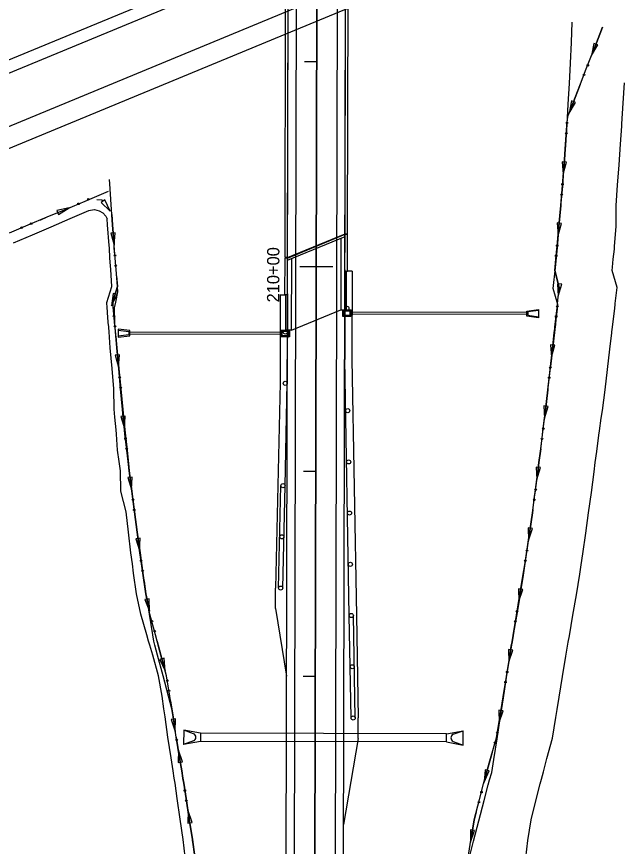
# Model space of a CAD drawing. Extents: x 1611108 to 1749517, y 619561 to 797725.
# Drawn here: x 1717467 to 1717763.5, y 765954.9 to 766360 of the extents above; entities that cross this region are included whole.
import ezdxf

# ---------------------------------------------------------------- set-up
doc = ezdxf.new("R2010")
doc.units = 0
for name, color, linetype in [('Level 8', 7, 'Continuous'), ('R_Bridge', 7, 'Continuous'), ('R_Ditch', 7, 'Continuous'), ('R_Drainage', 7, 'Continuous'), ('R_Guardrail', 7, 'Continuous'), ('R_Horz Alg', 7, 'Continuous'), ('R_Horz Alg Stationing_Side Road', 7, 'Continuous'), ('R_Proposed Const Limits', 7, 'Continuous'), ('R_Proposed Road', 7, 'Continuous'), ('R_Shld_GR', 7, 'Continuous'), ('R_Special Ditch', 7, 'Continuous')]:
    doc.layers.add(name, color=color, linetype=linetype)

msp = doc.modelspace()

# ---------------------------------------------------------------- linework, layer by layer
at = {"layer": 'Level 8'}
msp.add_line((1717616.46, 767638.01), (1717610.87, 765238.01), dxfattribs=at)
at = {"layer": 'R_Bridge'}
for p, q in [((1717627.24, 766253.93), (1717628.19, 766664.7)), ((1717628.49, 766253.93), (1717629.44, 766664.7)), ((1717597.96, 766242.32), (1717598.91, 766653.1)), ((1717599.21, 766242.32), (1717600.16, 766653.09)), ((1717599.21, 766242.32), (1717627.24, 766253.93)), ((1717627.24, 766253.93), (1717628.49, 766253.93)), ((1717599.21, 766242.09), (1717627.23, 766253.7)), ((1717599.21, 766241.01), (1717627.23, 766252.62)), ((1717627.19, 766235.7), (1717627.23, 766253.7)), ((1717627.23, 766253.7), (1717628.48, 766253.7)), ((1717628.44, 766235.7), (1717628.48, 766253.7)), ((1717597.92, 766224.1), (1717597.96, 766242.1)), ((1717599.21, 766242.32), (1717597.96, 766242.32)), ((1717599.21, 766242.09), (1717597.96, 766242.1)), ((1717599.17, 766224.09), (1717599.21, 766242.09)), ((1717627.19, 766235.7), (1717628.44, 766235.7)), ((1717599.17, 766224.09), (1717597.92, 766224.1))]:
    msp.add_line(p, q, dxfattribs=at)
at = {"layer": 'R_Ditch'}
for p, q in [((1717748.63, 766346.88), (1717747.45, 766340.9)), ((1717747.45, 766340.9), (1717750.6, 766346.11)), ((1717750.6, 766346.11), (1717748.63, 766346.88)), ((1717737.76, 766318.87), (1717736.57, 766312.9)), ((1717739.73, 766318.11), (1717737.76, 766318.87)), ((1717736.57, 766312.9), (1717739.73, 766318.11)), ((1717735.2, 766288.97), (1717733.09, 766289.13)), ((1717733.09, 766289.13), (1717733.69, 766283.07)), ((1717733.69, 766283.07), (1717735.2, 766288.97)), ((1717510.07, 766270.49), (1717508.34, 766269.28)), ((1717512.65, 766264.97), (1717510.07, 766270.49)), ((1717492.61, 766266.61), (1717486.67, 766265.27)), ((1717487.49, 766263.31), (1717492.61, 766266.61)), ((1717508.34, 766269.28), (1717512.65, 766264.97)), ((1717486.67, 766265.27), (1717487.49, 766263.31)), ((1717732.75, 766259.01), (1717730.65, 766259.21)), ((1717730.65, 766259.21), (1717731.15, 766253.14)), ((1717731.15, 766253.14), (1717732.75, 766259.01)), ((1717515.16, 766254.39), (1717513.05, 766254.23)), ((1717513.05, 766254.23), (1717514.56, 766248.33)), ((1717514.56, 766248.33), (1717515.16, 766254.39)), ((1717732.97, 766229.35), (1717730.86, 766229.57)), ((1717730.86, 766229.57), (1717731.28, 766223.5)), ((1717731.28, 766223.5), (1717732.97, 766229.35)), ((1717514.09, 766224.84), (1717513.34, 766218.79)), ((1717513.34, 766218.79), (1717516.11, 766224.22)), ((1717516.11, 766224.22), (1717514.09, 766224.84)), ((1717729.63, 766199.49), (1717727.52, 766199.73)), ((1717727.52, 766199.73), (1717727.9, 766193.65)), ((1717727.9, 766193.65), (1717729.63, 766199.49)), ((1717517.27, 766194.88), (1717515.17, 766194.69)), ((1717515.17, 766194.69), (1717516.77, 766188.81)), ((1717516.77, 766188.81), (1717517.27, 766194.88)), ((1717726.27, 766169.64), (1717724.17, 766169.88)), ((1717724.17, 766169.88), (1717724.52, 766163.8)), ((1717724.52, 766163.8), (1717726.27, 766169.64)), ((1717520.05, 766164.98), (1717517.94, 766164.77)), ((1717519.59, 766158.91), (1717520.05, 766164.98)), ((1717517.94, 766164.77), (1717519.59, 766158.91)), ((1717722.62, 766139.81), (1717720.52, 766140.08)), ((1717720.52, 766140.08), (1717720.81, 766133.99)), ((1717720.81, 766133.99), (1717722.62, 766139.81)), ((1717523.4, 766135.16), (1717521.3, 766134.9)), ((1717521.3, 766134.9), (1717523.08, 766129.07)), ((1717523.08, 766129.07), (1717523.4, 766135.16)), ((1717718.63, 766110.02), (1717716.53, 766110.33)), ((1717716.53, 766110.33), (1717716.69, 766104.24)), ((1717716.69, 766104.24), (1717718.63, 766110.02)), ((1717527.25, 766105.38), (1717525.16, 766105.09)), ((1717525.16, 766105.09), (1717527.02, 766099.29)), ((1717527.02, 766099.29), (1717527.25, 766105.38)), ((1717713.99, 766080.32), (1717711.9, 766080.67)), ((1717711.9, 766080.67), (1717711.95, 766074.58)), ((1717711.95, 766074.58), (1717713.99, 766080.32)), ((1717531.68, 766075.73), (1717529.6, 766075.33)), ((1717531.78, 766069.64), (1717531.68, 766075.73)), ((1717529.6, 766075.33), (1717531.78, 766069.64)), ((1717709.1, 766050.69), (1717707.01, 766051.03)), ((1717707.01, 766051.03), (1717707.09, 766044.94)), ((1717707.09, 766044.94), (1717709.1, 766050.69)), ((1717538.95, 766046.68), (1717536.9, 766046.13)), ((1717536.9, 766046.13), (1717539.48, 766040.61)), ((1717539.48, 766040.61), (1717538.95, 766046.68)), ((1717704.32, 766021.04), (1717702.23, 766021.37)), ((1717702.23, 766021.37), (1717702.36, 766015.27)), ((1717702.36, 766015.27), (1717704.32, 766021.04)), ((1717544.59, 766017.09), (1717542.49, 766016.77)), ((1717542.49, 766016.77), (1717544.45, 766011)), ((1717544.45, 766011), (1717544.59, 766017.09)), ((1717695.56, 765992.24), (1717695.05, 765986.17)), ((1717695.05, 765986.17), (1717697.61, 765991.7)), ((1717697.61, 765991.7), (1717695.56, 765992.24)), ((1717690.46, 765962.63), (1717688.37, 765963)), ((1717688.37, 765963), (1717688.38, 765956.9)), ((1717688.38, 765956.9), (1717690.46, 765962.63))]:
    msp.add_line(p, q, dxfattribs=at)
for points in [[(1717687.85, 765948.93), (1717689.95, 765957.36), (1717692.47, 765967.35), (1717695.03, 765977.34), (1717697, 765984.91), (1717697.74, 765987.34), (1717698.83, 765990.91), (1717699.87, 765997.33), (1717701.4, 766007.33), (1717702.91, 766017.33), (1717703.5, 766021.2), (1717704.46, 766027.32), (1717706.06, 766037.32), (1717707.68, 766047.32), (1717708.47, 766052.2), (1717708.81, 766054.21), (1717709.32, 766057.31), (1717710.99, 766067.31), (1717712.42, 766075.87), (1717712.65, 766077.3), (1717714.25, 766087.3), (1717715.78, 766097.3), (1717717.24, 766107.29), (1717718.62, 766117.29), (1717719.73, 766125.86), (1717719.93, 766127.29), (1717721.26, 766137.28), (1717721.51, 766139.18), (1717722.54, 766147.28), (1717723.78, 766157.28), (1717724.96, 766167.28), (1717726.12, 766177.27), (1717727.37, 766187.27), (1717727.61, 766189.17), (1717728.58, 766197.27), (1717729.74, 766207.26), (1717729.78, 766207.55), (1717729.81, 766207.81), (1717729.81, 766207.83), (1717729.84, 766208.12), (1717730.26, 766211.87), (1717730.86, 766217.26), (1717731.04, 766218.99), (1717731.09, 766219.49), (1717728.84, 766227.27), (1717729.85, 766237.26), (1717730.81, 766247.26), (1717731.72, 766257.26), (1717732.58, 766267.26), (1717733.4, 766277.26), (1717734.16, 766287.25), (1717734.87, 766297.25), (1717735.54, 766307.25), (1717736.15, 766317.25), (1717736.71, 766327.25), (1717737.23, 766337.25), (1717737.69, 766347.25), (1717738.11, 766357.25)], [(1717687.33, 765949.41), (1717688.55, 765957.83), (1717690.29, 765967.83), (1717692.86, 765977.82), (1717694.84, 765985.39), (1717695.48, 765987.82), (1717696.43, 765991.39), (1717698.15, 765997.81), (1717701.06, 766007.81), (1717702.75, 766017.8), (1717703.35, 766021.67), (1717704.31, 766027.8), (1717705.92, 766037.79), (1717707.55, 766047.79), (1717708.35, 766052.68), (1717708.68, 766054.68), (1717709.18, 766057.79), (1717710.81, 766067.78), (1717712.49, 766077.78), (1717714.13, 766087.78), (1717714.87, 766092.34), (1717715.71, 766097.77), (1717717.22, 766107.77), (1717718.65, 766117.77), (1717720.01, 766127.76), (1717721.29, 766137.76), (1717721.85, 766142.33), (1717722.54, 766147.76), (1717723.53, 766155.65), (1717723.79, 766157.75), (1717724.53, 766163.96), (1717724.98, 766167.75), (1717726.13, 766177.75), (1717727.22, 766187.75), (1717728.36, 766197.74), (1717729.29, 766205.64), (1717729.54, 766207.74), (1717729.57, 766208.03), (1717729.6, 766208.29), (1717729.6, 766208.3), (1717729.63, 766208.59), (1717730.06, 766212.34), (1717730.66, 766217.74), (1717730.85, 766219.46), (1717730.9, 766219.96), (1717731.73, 766227.73), (1717729.5, 766236.02), (1717729.67, 766237.74), (1717730.05, 766241.56), (1717730.53, 766246.54), (1717730.65, 766247.74), (1717731.57, 766257.74), (1717732.45, 766267.73), (1717733.27, 766277.73), (1717734.05, 766287.73), (1717734.77, 766297.73), (1717735.38, 766306.62), (1717735.45, 766307.73), (1717736.07, 766311.61), (1717742.09, 766327.13), (1717744.94, 766334.41), (1717749.39, 766345.92), (1717752.9, 766354.87)], [(1717752.9, 766354.87), (1717749.39, 766345.92), (1717747.45, 766340.9)], [(1717742, 766326.88), (1717736.57, 766312.9)], [(1717742.01, 766326.92), (1717742, 766326.88)], [(1717734.79, 766298.03), (1717734.77, 766297.73), (1717734.05, 766287.73), (1717733.69, 766283.07)], [(1717734.79, 766298.06), (1717734.79, 766298.03)], [(1717553.97, 765949.72), (1717552.75, 765958.15), (1717551.26, 765968.15), (1717549.73, 765978.16), (1717548.55, 765985.73), (1717548.16, 765988.16), (1717547.59, 765991.74), (1717546.55, 765998.17), (1717544.89, 766008.17), (1717543.35, 766018.17), (1717542.74, 766022.04), (1717541.13, 766028.18), (1717538.46, 766038.18), (1717535.77, 766048.19), (1717534.45, 766053.08), (1717533.91, 766055.09), (1717533.4, 766058.2), (1717531.8, 766068.2), (1717530.5, 766076.77), (1717530.28, 766078.2), (1717528.8, 766088.21), (1717527.38, 766098.21), (1717526, 766108.21), (1717524.67, 766118.22), (1717523.57, 766126.79), (1717523.39, 766128.22), (1717522.16, 766138.22), (1717521.93, 766140.12), (1717521.04, 766148.22), (1717520.02, 766158.23), (1717519.03, 766168.23), (1717518.01, 766178.23), (1717517.06, 766188.23), (1717516.88, 766190.13), (1717516.03, 766198.24), (1717515.02, 766208.24), (1717514.99, 766208.53), (1717514.96, 766208.79), (1717514.83, 766217.84), (1717515.47, 766220.55), (1717516.47, 766225.61), (1717516.23, 766228.24), (1717515.52, 766236.52), (1717515.37, 766238.24), (1717515.06, 766242.06), (1717514.56, 766248.24), (1717513.8, 766258.24), (1717513.09, 766268.24), (1717512.43, 766278.25), (1717512.3, 766280.43)], [(1717463.5, 766254.41), (1717472.72, 766258.27), (1717481.94, 766262.14), (1717491.17, 766266), (1717500.39, 766269.86), (1717509.62, 766273.71), (1717511.92, 766274.67)], [(1717506.23, 766270.75), (1717508.64, 766270.45), (1717509.28, 766269.95)], [(1717478.78, 766260.81), (1717481.94, 766262.14), (1717491.17, 766266), (1717492.61, 766266.61)], [(1717732.48, 766268.08), (1717732.45, 766267.73), (1717731.57, 766257.74), (1717731.15, 766253.14)], [(1717732.48, 766268.12), (1717732.48, 766268.08)], [(1717553.97, 765949.72), (1717552.75, 765958.15), (1717551.26, 765968.15), (1717549.73, 765978.16), (1717548.55, 765985.73), (1717548.16, 765988.16), (1717547.59, 765991.74), (1717546.55, 765998.17), (1717544.89, 766008.17), (1717543.35, 766018.17), (1717542.74, 766022.04), (1717541.77, 766028.18), (1717540.14, 766038.18), (1717537.45, 766048.19), (1717536.13, 766053.08), (1717535.59, 766055.09), (1717534.75, 766058.19), (1717532.06, 766068.2), (1717530.12, 766078.2), (1717528.6, 766088.21), (1717527.94, 766092.78), (1717527.17, 766098.21), (1717525.79, 766108.21), (1717524.46, 766118.22), (1717523.18, 766128.22), (1717521.95, 766138.22), (1717521.41, 766142.79), (1717520.77, 766148.23), (1717519.88, 766156.13), (1717519.66, 766158.23), (1717519.04, 766164.44), (1717518.67, 766168.23), (1717517.76, 766178.23), (1717516.82, 766188.23), (1717515.9, 766198.24), (1717515.23, 766206.14), (1717515.02, 766208.24), (1717514.99, 766208.53), (1717514.97, 766208.79), (1717514.96, 766208.8), (1717514.94, 766209.09), (1717514.57, 766212.85), (1717514.06, 766218.24), (1717513.9, 766219.97), (1717513.85, 766220.47), (1717516.23, 766228.24), (1717515.52, 766236.52), (1717515.37, 766238.24), (1717515.06, 766242.06), (1717514.66, 766247.04), (1717514.56, 766248.24), (1717513.8, 766258.24), (1717513.44, 766263.29)], [(1717513.44, 766263.29), (1717513.8, 766258.24), (1717514.56, 766248.33)], [(1717478.74, 766260.8), (1717478.78, 766260.81)], [(1717729.72, 766238.17), (1717729.67, 766237.74), (1717729.5, 766236.02), (1717731.73, 766227.73), (1717731.28, 766223.5)], [(1717729.72, 766238.2), (1717729.72, 766238.17)], [(1717515.79, 766233.34), (1717516.23, 766228.24), (1717513.85, 766220.47), (1717513.9, 766219.97), (1717514.02, 766218.72)], [(1717515.79, 766233.38), (1717515.79, 766233.34)], [(1717729.63, 766208.55), (1717729.6, 766208.3), (1717729.6, 766208.29), (1717729.57, 766208.03), (1717729.54, 766207.74), (1717729.29, 766205.64), (1717728.36, 766197.74), (1717727.9, 766193.65)], [(1717729.63, 766208.59), (1717729.63, 766208.55)], [(1717515.43, 766203.79), (1717515.43, 766203.75)], [(1717515.43, 766203.75), (1717515.9, 766198.24), (1717516.77, 766188.81)], [(1717726.23, 766178.7), (1717726.13, 766177.75), (1717724.98, 766167.75), (1717724.53, 766163.96), (1717724.52, 766163.8)], [(1717726.24, 766178.74), (1717726.23, 766178.7)], [(1717518.16, 766173.87), (1717518.16, 766173.84)], [(1717518.16, 766173.84), (1717518.67, 766168.23), (1717519.04, 766164.44), (1717519.59, 766158.91)], [(1717722.68, 766148.88), (1717722.54, 766147.76), (1717721.85, 766142.33), (1717721.29, 766137.76), (1717720.81, 766133.99)], [(1717722.69, 766148.91), (1717722.68, 766148.88)], [(1717521.27, 766144), (1717521.27, 766143.96)], [(1717521.27, 766143.96), (1717521.41, 766142.79), (1717521.95, 766138.22), (1717523.08, 766129.07)], [(1717718.83, 766119.09), (1717718.65, 766117.77), (1717717.22, 766107.77), (1717716.69, 766104.24)], [(1717718.84, 766119.12), (1717718.83, 766119.09)], [(1717525, 766114.19), (1717525, 766114.16)], [(1717525, 766114.16), (1717525.79, 766108.21), (1717527.02, 766099.29)], [(1717714.39, 766089.38), (1717714.13, 766087.78), (1717712.49, 766077.78), (1717711.95, 766074.58)], [(1717714.4, 766089.42), (1717714.39, 766089.38)], [(1717529.17, 766084.45), (1717529.18, 766084.41)], [(1717529.18, 766084.41), (1717530.12, 766078.2), (1717531.78, 766069.64)], [(1717709.5, 766059.74), (1717709.18, 766057.79), (1717708.68, 766054.68), (1717708.35, 766052.68), (1717707.55, 766047.79), (1717707.09, 766044.94)], [(1717709.51, 766059.78), (1717709.5, 766059.74)], [(1717535.58, 766055.13), (1717535.59, 766055.1)], [(1717535.59, 766055.1), (1717535.59, 766055.09), (1717536.13, 766053.08), (1717537.45, 766048.19), (1717539.48, 766040.61)], [(1717704.68, 766030.09), (1717704.31, 766027.8), (1717703.35, 766021.67), (1717702.75, 766017.8), (1717702.32, 766015.28)], [(1717704.69, 766030.13), (1717704.68, 766030.09)], [(1717542.14, 766025.86), (1717542.14, 766025.82)], [(1717542.14, 766025.82), (1717542.74, 766022.04), (1717543.35, 766018.17), (1717544.45, 766011)], [(1717553.97, 765949.72), (1717552.75, 765958.15), (1717551.26, 765968.15), (1717549.73, 765978.16), (1717548.55, 765985.73), (1717548.16, 765988.16), (1717547.59, 765991.74), (1717546.55, 765998.17), (1717544.89, 766008.17)], [(1717698.97, 766000.65), (1717698.15, 765997.81), (1717696.43, 765991.39), (1717695.48, 765987.82), (1717695.05, 765986.17)], [(1717698.98, 766000.68), (1717698.97, 766000.65)], [(1717691.26, 765971.62), (1717690.29, 765967.83), (1717688.55, 765957.83), (1717688.41, 765956.9)], [(1717691.27, 765971.65), (1717691.26, 765971.62)]]:
    msp.add_lwpolyline(points, dxfattribs=at)
for centre in [(1717745.68, 766336.22), (1717743.86, 766331.55), (1717735.53, 766308.03), (1717735.17, 766303.03), (1717733.33, 766278.07), (1717501.99, 766270.77), (1717732.92, 766273.08), (1717497.22, 766268.57), (1717474.13, 766258.91), (1717469.51, 766256.97), (1717730.72, 766248.15), (1717514.99, 766243.34), (1717730.24, 766243.16), (1717515.4, 766238.35), (1717730.78, 766218.51), (1717514.52, 766213.74), (1717730.23, 766213.54), (1717515.01, 766208.76), (1717727.36, 766188.67), (1717517.27, 766183.83), (1717726.81, 766183.69), (1717517.74, 766178.84), (1717723.95, 766158.83), (1717520.16, 766153.93), (1717723.34, 766153.86), (1717520.73, 766148.95), (1717720.21, 766129.02), (1717523.75, 766124.11), (1717719.54, 766124.06), (1717524.38, 766119.14), (1717715.98, 766099.29), (1717527.76, 766094.34), (1717715.21, 766094.33), (1717528.47, 766089.38), (1717711.16, 766069.64), (1717533.02, 766064.79), (1717710.35, 766064.69), (1717534.32, 766059.96), (1717706.32, 766039.99), (1717540.57, 766035.73), (1717705.52, 766035.05), (1717541.38, 766030.79), (1717701.52, 766010.34), (1717700.41, 766005.46), (1717693.81, 765981.32), (1717692.55, 765976.47)]:
    msp.add_circle(centre, 0.375, dxfattribs=at)
at = {"layer": 'R_Drainage'}
for p, q in [((1717715.92, 766214.46), (1717629.64, 766214.66)), ((1717715.93, 766215.46), (1717629.65, 766215.66)), ((1717596.62, 766205.74), (1717522.2, 766205.91)), ((1717596.62, 766204.74), (1717522.2, 766204.91)), ((1717548.53, 766011.66), (1717548.51, 766004.66)), ((1717556.7, 766010.14), (1717548.53, 766011.66)), ((1717553.34, 766009.87), (1717548.53, 766011.66)), ((1717676.7, 766009.86), (1717684.87, 766011.34)), ((1717680.06, 766009.57), (1717684.87, 766011.34)), ((1717684.85, 766004.34), (1717684.87, 766011.34)), ((1717556.7, 766010.14), (1717556.69, 766006.14)), ((1717676.7, 766009.86), (1717556.7, 766010.14)), ((1717676.69, 766005.86), (1717676.7, 766009.86)), ((1717553.33, 766006.43), (1717548.51, 766004.66)), ((1717556.69, 766006.14), (1717548.51, 766004.66)), ((1717676.69, 766005.86), (1717556.69, 766006.14)), ((1717676.69, 766005.86), (1717684.85, 766004.34)), ((1717680.05, 766006.13), (1717684.85, 766004.34))]:
    msp.add_line(p, q, dxfattribs=at)
for points in [[(1717630.15, 766216.78), (1717630.14, 766213.55), (1717626.14, 766213.56), (1717626.15, 766216.79)], [(1717629.65, 766216.28), (1717629.64, 766214.05), (1717626.64, 766214.06), (1717626.65, 766216.29)], [(1717715.93, 766216.21), (1717721.6, 766216.95), (1717721.59, 766212.95), (1717715.92, 766213.71)], [(1717522.21, 766206.66), (1717516.54, 766207.42), (1717516.53, 766203.42), (1717522.2, 766204.16)], [(1717600.13, 766206.84), (1717600.12, 766203.61), (1717596.12, 766203.62), (1717596.13, 766206.85)], [(1717599.62, 766206.34), (1717599.62, 766204.11), (1717596.62, 766204.12), (1717596.62, 766206.35)]]:
    msp.add_lwpolyline(points, close=True, dxfattribs=at)
for points in [[(1717721.6, 766216.45), (1717716.43, 766215.77), (1717716.42, 766214.15), (1717721.59, 766213.46)], [(1717516.54, 766206.92), (1717521.7, 766206.22), (1717521.7, 766204.6), (1717516.53, 766203.93)]]:
    msp.add_lwpolyline(points, dxfattribs=at)
for centre, start, end in [((1717552.69, 766008.15), 290.1852, 69.548), ((1717680.69, 766007.85), 110.1852, 249.548)]:
    msp.add_arc(centre, 1.83, start, end, dxfattribs=at)
at = {"layer": 'R_Guardrail'}
for p, q in [((1717627.19, 766236.3), (1717627.09, 766192.55)), ((1717599.17, 766224.69), (1717599.07, 766181.13)), ((1717629.3, 766067.55), (1717627.09, 766192.55)), ((1717597.95, 766130.94), (1717599.07, 766181.13)), ((1717594.83, 766080.99), (1717595.95, 766130.99)), ((1717596.83, 766080.95), (1717597.95, 766130.94)), ((1717632.18, 766017.58), (1717631.3, 766067.58)), ((1717630.19, 766017.54), (1717629.3, 766067.55))]:
    msp.add_line(p, q, dxfattribs=at)
for centre in [(1717628.15, 766217.57), (1717598.12, 766205.95), (1717598.06, 766180.95), (1717628.53, 766167.57), (1717628.98, 766142.57), (1717596.95, 766130.97), (1717629.42, 766117.57), (1717596.39, 766105.97), (1717629.86, 766092.57), (1717595.83, 766080.97), (1717630.3, 766067.56), (1717630.74, 766042.56), (1717631.19, 766017.56)]:
    msp.add_circle(centre, 1, dxfattribs=at)
at = {"layer": 'R_Horz Alg'}
msp.add_line((1717610.87, 765238.01), (1717616.46, 767638.01), dxfattribs=at)
at = {"layer": 'R_Horz Alg Stationing_Side Road'}
for points in [[(1717607.43, 766338.02), (1717613.43, 766338.01)], [(1717605.2, 766238.03), (1717621.2, 766237.99)], [(1717606.97, 766138.02), (1717612.97, 766138.01)], [(1717606.73, 766038.03), (1717612.73, 766038.01)]]:
    msp.add_lwpolyline(points, dxfattribs=at)
at = {"layer": 'R_Proposed Const Limits'}
for points in [[(1717715.37, 765949.34), (1717716.47, 765957.77), (1717718.1, 765967.77), (1717720.53, 765977.76), (1717722.46, 765985.33), (1717723.07, 765987.75), (1717723.97, 765991.33), (1717725.65, 765997.75), (1717728.47, 766007.74), (1717730.13, 766017.74), (1717730.73, 766021.61), (1717731.69, 766027.73), (1717733.32, 766037.73), (1717734.99, 766047.73), (1717735.81, 766052.61), (1717736.15, 766054.62), (1717736.66, 766057.72), (1717738.36, 766067.72), (1717740.12, 766077.71), (1717741.75, 766087.71), (1717742.45, 766092.28), (1717743.26, 766097.71), (1717744.7, 766107.7), (1717746.07, 766117.7), (1717747.39, 766127.7), (1717748.69, 766137.7), (1717749.3, 766142.26), (1717750.06, 766147.69), (1717751.1, 766155.59), (1717751.38, 766157.69), (1717752.21, 766163.9), (1717752.76, 766167.69), (1717754.19, 766177.68), (1717755.32, 766187.68), (1717756.41, 766197.68), (1717757.35, 766205.58), (1717757.6, 766207.67), (1717757.64, 766207.96), (1717757.67, 766208.22), (1717757.67, 766208.24), (1717757.71, 766208.53), (1717758.15, 766212.28), (1717758.77, 766217.67), (1717758.97, 766219.4), (1717759.03, 766219.9), (1717759.91, 766227.67), (1717757.51, 766235.96), (1717757.69, 766237.67), (1717758.1, 766241.5), (1717758.61, 766246.47), (1717758.73, 766247.67), (1717759.44, 766257.67), (1717759.43, 766267.67), (1717760.19, 766277.67), (1717760.96, 766287.67), (1717761.67, 766297.67), (1717762.26, 766306.55), (1717762.33, 766307.66), (1717762.94, 766317.66), (1717763.5, 766327.63)], [(1717465.51, 766249.54), (1717474.75, 766253.36), (1717483.94, 766257.3), (1717493.08, 766261.36), (1717502.3, 766265.25), (1717502.99, 766265.52), (1717505.06, 766265.81), (1717507.32, 766265.15), (1717509.03, 766264.19), (1717510.6, 766262.58), (1717511.17, 766261.17)], [(1717549.32, 765949.73), (1717548.21, 765958.16), (1717546.83, 765968.16), (1717545.41, 765978.17), (1717544.3, 765985.74), (1717543.94, 765988.17), (1717543.4, 765991.75), (1717542.39, 765998.17), (1717540.76, 766008.18), (1717539.46, 766018.18), (1717538.92, 766022.05), (1717538.05, 766028.19), (1717536.28, 766038.19), (1717533.41, 766048.2), (1717532.01, 766053.09), (1717531.44, 766055.1), (1717530.54, 766058.2), (1717527.67, 766068.21), (1717525.55, 766078.21), (1717524.05, 766088.22), (1717523.48, 766092.79), (1717522.79, 766098.22), (1717521.62, 766108.22), (1717520.49, 766118.23), (1717517.86, 766128.23), (1717517.68, 766138.23), (1717517.09, 766142.8), (1717516.25, 766148.24), (1717515.75, 766156.14), (1717515.51, 766158.24), (1717514.97, 766164.45), (1717514.65, 766168.24), (1717514.44, 766178.24), (1717513.57, 766188.24), (1717512.73, 766198.24), (1717512.16, 766206.15), (1717511.98, 766208.25), (1717511.96, 766208.54), (1717511.94, 766208.8), (1717511.93, 766208.81), (1717511.91, 766209.1), (1717511.59, 766212.85), (1717511.15, 766218.25), (1717511.02, 766219.97), (1717510.98, 766220.47), (1717513.54, 766228.24), (1717512.94, 766236.53), (1717512.82, 766238.24), (1717512.57, 766242.07), (1717512.27, 766247.05), (1717512.2, 766248.25), (1717511.42, 766258.25), (1717511.17, 766261.17)]]:
    msp.add_lwpolyline(points, dxfattribs=at)
at = {"layer": 'R_Proposed Road'}
for p, q in [((1715977.87, 765723.64), (1723873.63, 768994.17)), ((1715980.17, 765718.1), (1723875.92, 768988.63)), ((1715989.35, 765695.93), (1723885.11, 768966.45)), ((1715993.18, 765686.69), (1723888.93, 768957.22)), ((1717597.57, 765538.05), (1717601.76, 767338.04)), ((1717601.57, 765538.04), (1717605.76, 767338.03)), ((1717621.57, 765537.99), (1717625.76, 767337.98)), ((1717625.57, 765537.98), (1717629.76, 767337.98)), ((1717625.23, 766251.83), (1717625.15, 766216.79)), ((1717601.13, 766206.84), (1717601.21, 766241.84)), ((1717627.94, 766216.78), (1717627.98, 766235.7)), ((1717598.33, 766206.85), (1717598.37, 766224.1)), ((1717601.13, 766206.84), (1717625.15, 766216.79)), ((1717625.15, 766216.79), (1717627.94, 766216.78)), ((1717601.13, 766206.84), (1717598.33, 766206.85))]:
    msp.add_line(p, q, dxfattribs=at)
at = {"layer": 'R_Shld_GR'}
for p, q in [((1717630.69, 766235.69), (1717628.44, 766235.7)), ((1717630.69, 766235.69), (1717630.59, 766192.54)), ((1717595.67, 766224.1), (1717595.57, 766181.14)), ((1717595.67, 766224.1), (1717597.92, 766224.1)), ((1717630.59, 766192.61), (1717632.8, 766067.61)), ((1717595.57, 766181.21), (1717594.45, 766131.02)), ((1717594.45, 766131.02), (1717593.33, 766080.95)), ((1717593.3, 766070.95), (1717593.33, 766080.95)), ((1717593.3, 766070.95), (1717598.73, 766037.91)), ((1717632.8, 766067.61), (1717633.69, 766017.54)), ((1717633.66, 766007.54), (1717633.69, 766017.54)), ((1717633.66, 766007.54), (1717626.56, 765965.55))]:
    msp.add_line(p, q, dxfattribs=at)
at = {"layer": 'R_Special Ditch'}
for p, q in [((1717545.93, 766001.91), (1717545.87, 765995.81)), ((1717547.95, 765996.16), (1717545.93, 766001.91)), ((1717545.87, 765995.81), (1717547.95, 765996.16)), ((1717550.64, 765972.24), (1717550.5, 765966.15)), ((1717552.59, 765966.47), (1717550.64, 765972.24)), ((1717550.5, 765966.15), (1717552.59, 765966.47))]:
    msp.add_line(p, q, dxfattribs=at)
for points in [[(1717544.89, 766008.17), (1717546.55, 765998.17), (1717547.59, 765991.74), (1717548.16, 765988.16), (1717548.55, 765985.73), (1717549.73, 765978.16), (1717551.26, 765968.15), (1717552.75, 765958.15), (1717553.97, 765949.72)], [(1717548.33, 765987.1), (1717548.16, 765988.16), (1717547.59, 765991.74), (1717546.55, 765998.17), (1717545.93, 766001.91)], [(1717548.34, 765987.06), (1717548.33, 765987.1)], [(1717552.86, 765957.4), (1717552.75, 765958.15), (1717551.26, 765968.15), (1717550.64, 765972.24)], [(1717552.86, 765957.37), (1717552.86, 765957.4)]]:
    msp.add_lwpolyline(points, dxfattribs=at)
for centre in [(1717545.07, 766006.84), (1717549.07, 765982.13), (1717549.85, 765977.18)]:
    msp.add_circle(centre, 0.375, dxfattribs=at)

# ---------------------------------------------------------------- texts
at = {"layer": 'R_Horz Alg Stationing_Side Road'}
msp.add_text('210+00', height=6, rotation=89.8667, dxfattribs=at).set_placement((1717595.16, 766220.41))

doc.saveas('drawing.dxf')
